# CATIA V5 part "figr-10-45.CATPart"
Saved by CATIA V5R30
Part number: Part1
Bounding box of the stored display mesh (mm): x -20 to 20, y -41.679 to 32.292, z -5.268 to 19.6
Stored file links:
  D:\PROJECTS\CATIA V56R 2020\Resources\Parts File\c10_catia_v5_6r2020_prt\figr-10-45.CATPart
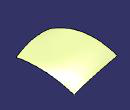
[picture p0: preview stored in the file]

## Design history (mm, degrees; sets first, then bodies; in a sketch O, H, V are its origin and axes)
Set1
  Plane1: type Offset, RefPlane yz-plane, Offset 20, reversed
  Plane2: type Offset, RefPlane yz-plane, Offset 20
  Sketch1 on Plane1, origin (-20, 0, 0), H (0, 1, 0), V (0, 0, 1)
    spline S1 through (-41.3356, 3.6998) (10.9718, 19.5196) (47.9697, 8.2926)
  Sketch2 on yz-plane, origin (0, 0, 0), H (0, 1, 0), V (0, 0, 1)
    spline S1 through (-41.087, 1.981) (-29.2011, 1.8342) (-9.0978, 3.8886) (28.3207, 0)
    point P1 (28.3207, 0)
    coincidence: P1 H
  Sketch3 on Plane2, origin (20, 0, 0), H (0, 1, 0), V (0, 0, 1)
    spline S1 through (-41.7094, -2.237) (-14.4323, 0.9381) (25.2566, -5.2678)
  Plane3: type Offset, RefPlane yz-plane, Offset 10
  Sketch4 on Plane3, origin (10, 0, 0), H (0, 1, 0), V (0, 0, 1)
    spline S1 through (-45.2274, 0) (26.2784, 6.3461) (36.8255, 3.6647)
    point P1 (-45.2274, 0)
    coincidence: P1 H
  Sweep1: type Conic, Guide ({sweepconicextendedguide Guide Sketch1, Reference Sketch2, Angle 15}; {sweepconicextendedguide Guide Sketch3, Reference Sketch4, Angle 0}), Parameter 0.5
Body1 (main body)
